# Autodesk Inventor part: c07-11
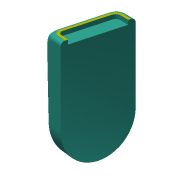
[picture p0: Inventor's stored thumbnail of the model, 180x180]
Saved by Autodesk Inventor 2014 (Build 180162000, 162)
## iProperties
Created: 2010-12
Part Number: c07-11
Material: Generic
Document SubType Name: Modeling
Designer: Beta-8540w
Density: 1 g/cm^3
Appearance: Smooth - Aqua
Author: Beta-8540w
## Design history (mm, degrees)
sketch "Sketch1"
  geometry: L1 (-25, 0)-(25, 0); L2 (25, 0)-(25, 80); L3 (25, 80)-(-25, 80); L4 (-25, 80)-(-25, 0); 2 further points
  constraints: 8 end point, 2 parallel, 1 coincident, 1 horizontal, 1 midpoint, 1 perpendicular
  dimensions: "d0" = 50 distance of L3.end L2.end; "d1" = 80 distance of L2.end L1.end
extrude "Extrusion1" new body sketch "Sketch1" distance "d2" = 15; taper "d3" = 0 deg
feature "FaceDraft1" dims angle "d4" = -2 deg
fillet "Fillet1"
fillet "Fillet2" dims "d5" = 8, "d6" = 8, "d7" = 8, "d8" = 8, "d9" = 8, "d10" = 8, "d11" = 3, "d12" = 3, "d13" = 3, "d14" = 6, "d15" = 5
sketch "Sketch2"
  geometry: L1 (5.522, 12)-(38.474, 12) reference; L2 (0, 0)-(43.996, 0) reference; L3 (41.757, 6.83)-(41.995, 0); L4 (41.925, 2)-(2.071, 2); L5 (2.001, 0)-(2.24, 6.83); L6 (5.522, 10)-(38.474, 10); A1 r 5.284 centre (38.474, 6.716) between (43.755, 6.9) and (38.474, 12) reference; A2 r 5.284 centre (5.522, 6.716) between (5.522, 12) and (0.241, 6.9) reference; A3 r 3.284 centre (38.474, 6.716) between (41.757, 6.83) and (38.474, 10); A4 r 3.284 centre (5.522, 6.716) between (5.522, 10) and (2.24, 6.83); 1 further point
  constraints: 8 end point, 4 point on circle, 4 point on line, 2 centre point, 1 other
  dimensions: "d16" = 2 radial gap between concentric circles of A2 A4
extrude "Extrusion2" cut sketch "Sketch2" distance "d17" = 3; taper "d18" = 0 deg
body "Solid1"
